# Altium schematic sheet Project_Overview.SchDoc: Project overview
size A4; Date: Not used; ApprovedBy: Not used; CheckedBy: Not used; Author: Not used; CompanyName: STMicroelectronics; DrawnBy: Not used; Engineer: Not used; Organization: Not used; Address1: Not used; Address2: Not used; Address3: Not used; Address4: Not used; DocumentNumber: MB1260; Revision: Not used; SheetNumber: 1; SheetTotal: 13
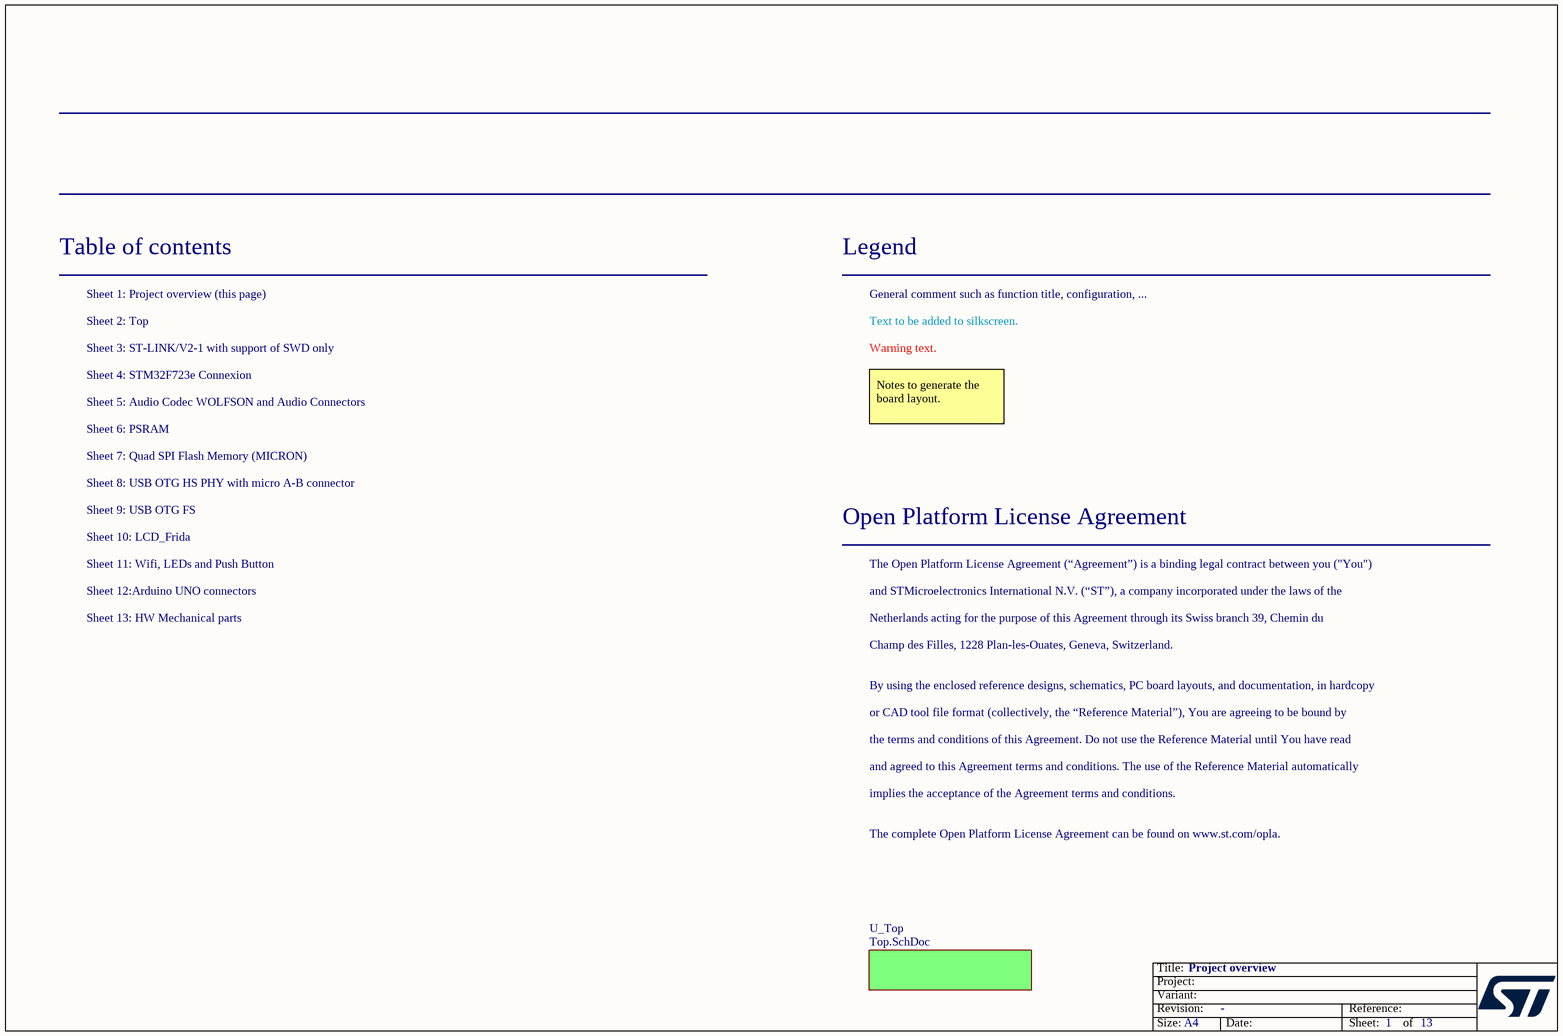
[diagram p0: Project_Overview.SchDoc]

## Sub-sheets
U_Top = Top.SchDoc: no entries

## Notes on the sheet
- Table of contents
- Sheet 1: Project overview (this page)
- Legend
- General comment such as function title, configuration, ...
- Sheet 2: Top
- Sheet 3: ST-LINK/V2-1 with support of SWD only
- Sheet 4: STM32F723e Connexion
- Text to be added to silkscreen.
- Warning text.
- Sheet 6: PSRAM
- Sheet 5: Audio Codec WOLFSON and Audio Connectors
- Notes to generate the board layout.
- Sheet 7: Quad SPI Flash Memory (MICRON)
- Sheet 9: USB OTG FS
- Sheet 8: USB OTG HS PHY with micro A-B connector
- Sheet 10: LCD_Frida
- Sheet 11: Wifi, LEDs and Push Button
- Open Platform License Agreement
- The Open Platform License Agreement (“Agreement”) is a binding legal contract between you ("You")
- Sheet 13: HW Mechanical parts
- Sheet 12:Arduino UNO connectors
- and STMicroelectronics International N.V. (“ST”), a company incorporated under the laws of the
- Netherlands acting for the purpose of this Agreement through its Swiss branch 39, Chemin du
- Champ des Filles, 1228 Plan-les-Ouates, Geneva, Switzerland.
- By using the enclosed reference designs, schematics, PC board layouts, and documentation, in hardcopy
- or CAD tool file format (collectively, the “Reference Material”), You are agreeing to be bound by
- the terms and conditions of this Agreement. Do not use the Reference Material until You have read
- and agreed to this Agreement terms and conditions. The use of the Reference Material automatically
- implies the acceptance of the Agreement terms and conditions.
- The complete Open Platform License Agreement can be found on www.st.com/opla.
